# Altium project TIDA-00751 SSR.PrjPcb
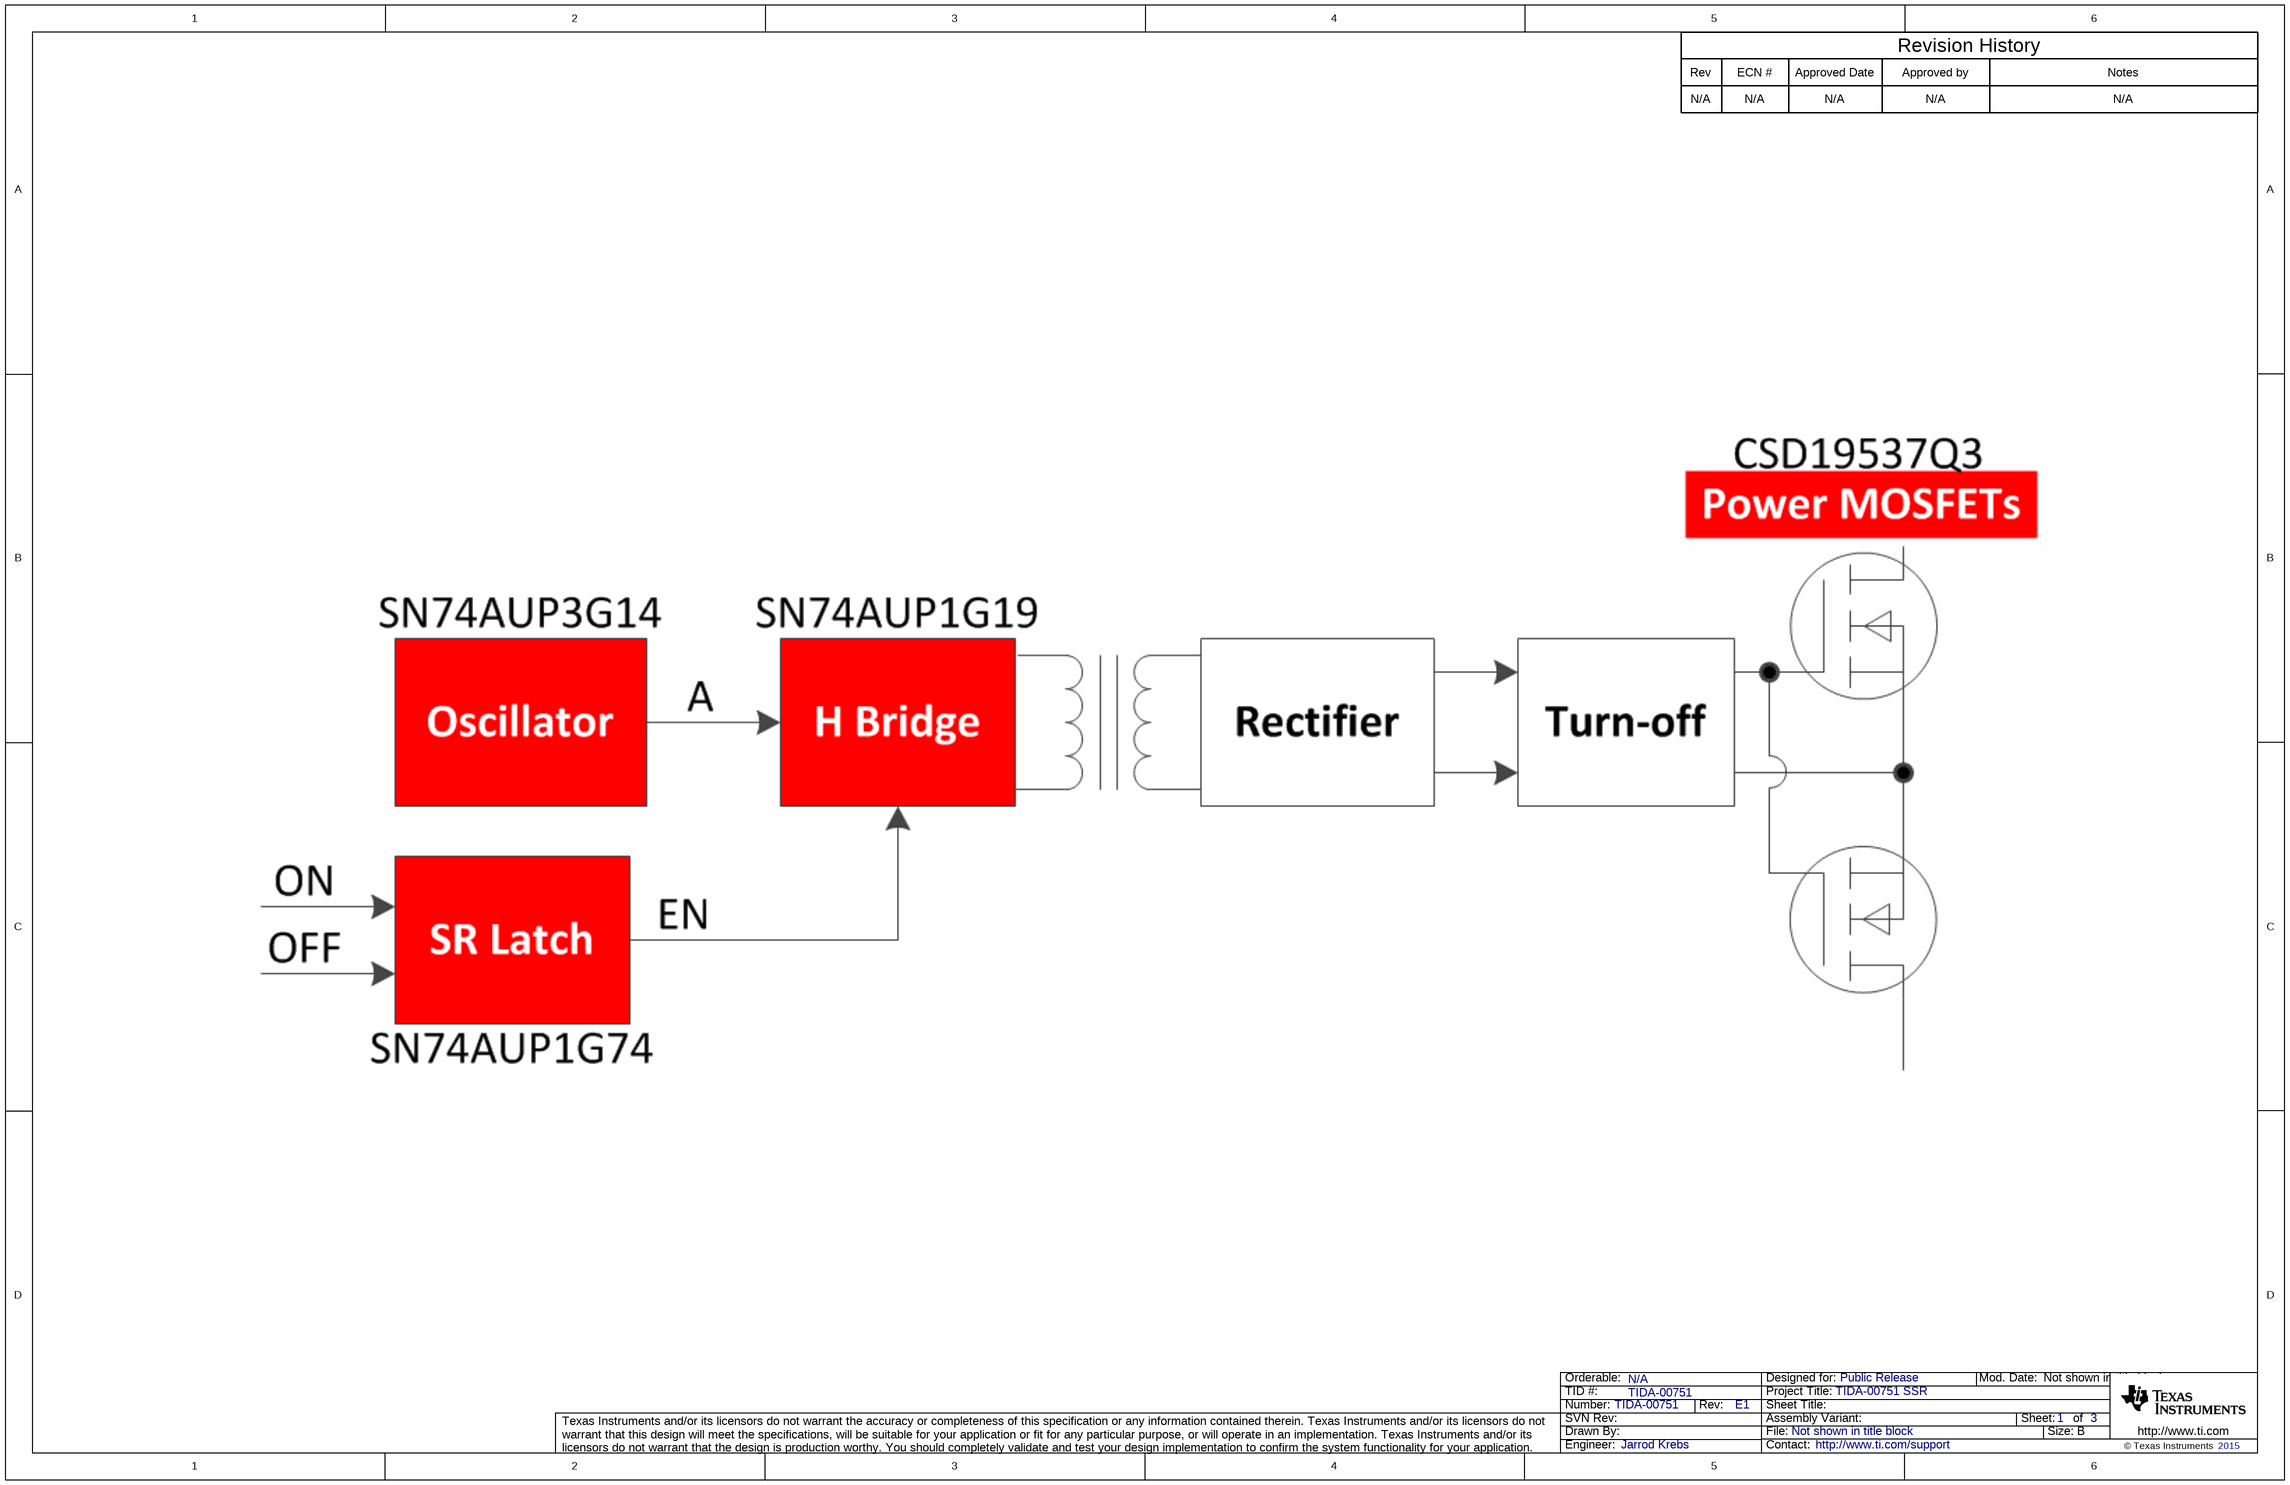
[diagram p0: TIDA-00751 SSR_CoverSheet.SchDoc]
CopyrightYear: 2015; EVM_Orderable: N/A; PCB_Layout: Who did the Layout?; PCB_Rev: E1; PRJ_Customer: Public Release; PRJ_Engineer: Jarrod Krebs; PRJ_Number: TIDA-00751; PRJ_Title: TIDA-00751 SSR; SCH_Rev: E1; TechSupport: http://www.ti.com/support; TID: TIDA-00751
3 sheets, 78 parts. Net scope: global (net labels, ports and power ports of the same name join across sheets).
Board file: TIDA-00751 SSR_TID.PcbDoc
Sheets:
  TIDA-00751 SSR_CoverSheet.SchDoc
  TIDA-00751 SSR_OSC+Relay.SchDoc
  TIDA-00751 SSR_TID_Hardware.SchDoc

## Sheet TIDA-00751 SSR_CoverSheet.SchDoc
size 431 x 279 mm; Date: Not shown in title block; ApprovedBy: Not shown in title block; CheckedBy: Not shown in title block; Author: Not shown in title block; CompanyName: Not shown in title block; Engineer: Not shown in title block; Organization: Not shown in title block; Address1: Not shown in title block; Address2: Not shown in title block; Address3: Not shown in title block; Address4: Not shown in title block; DocumentNumber: 1; Revision: Use project parameter SCH_Rev; SheetNumber: 1; SheetTotal: 3; PageSetup: Record=PageOptions¦CenterHorizontal=True¦CenterVertical=True¦PrintScale=1.00¦XCorrection=1.00¦YCorrection=1.00¦PrintKind=0¦BorderSize=5000000¦LeftOffset=0¦BottomOffset=0¦Orientation=2¦PaperLength=1000¦PaperWidth=1000¦Scale=100¦PaperSource=15¦PrintQuality=600¦MediaType=1¦DitherType=10¦PaperKind=Letter¦PrintScaleMode=1

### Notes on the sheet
- Rev
- N/A
- ECN #
- Approved Date
- Approved by
- Revision History
- Notes

## Sheet TIDA-00751 SSR_OSC+Relay.SchDoc
size 431 x 279 mm; Date: Not shown in title block; ApprovedBy: Not shown in title block; CheckedBy: Not shown in title block; Author: Not shown in title block; CompanyName: Not shown in title block; Engineer: Not shown in title block; Organization: Not shown in title block; Address1: Not shown in title block; Address2: Not shown in title block; Address3: Not shown in title block; Address4: Not shown in title block; DocumentNumber: 1; Revision: Use project parameter SCH_Rev; SheetNumber: 2; SheetTotal: 3; PageSetup: Record=PageOptions¦CenterHorizontal=True¦CenterVertical=True¦PrintScale=1.00¦XCorrection=1.00¦YCorrection=1.00¦PrintKind=0¦BorderSize=5000000¦LeftOffset=0¦BottomOffset=0¦Orientation=2¦PaperLength=1000¦PaperWidth=1000¦Scale=100¦PaperSource=15¦PrintQuality=-3¦MediaType=1¦DitherType=10¦PrintScaleMode=1¦PaperKind=Letter¦PaperIndex=1
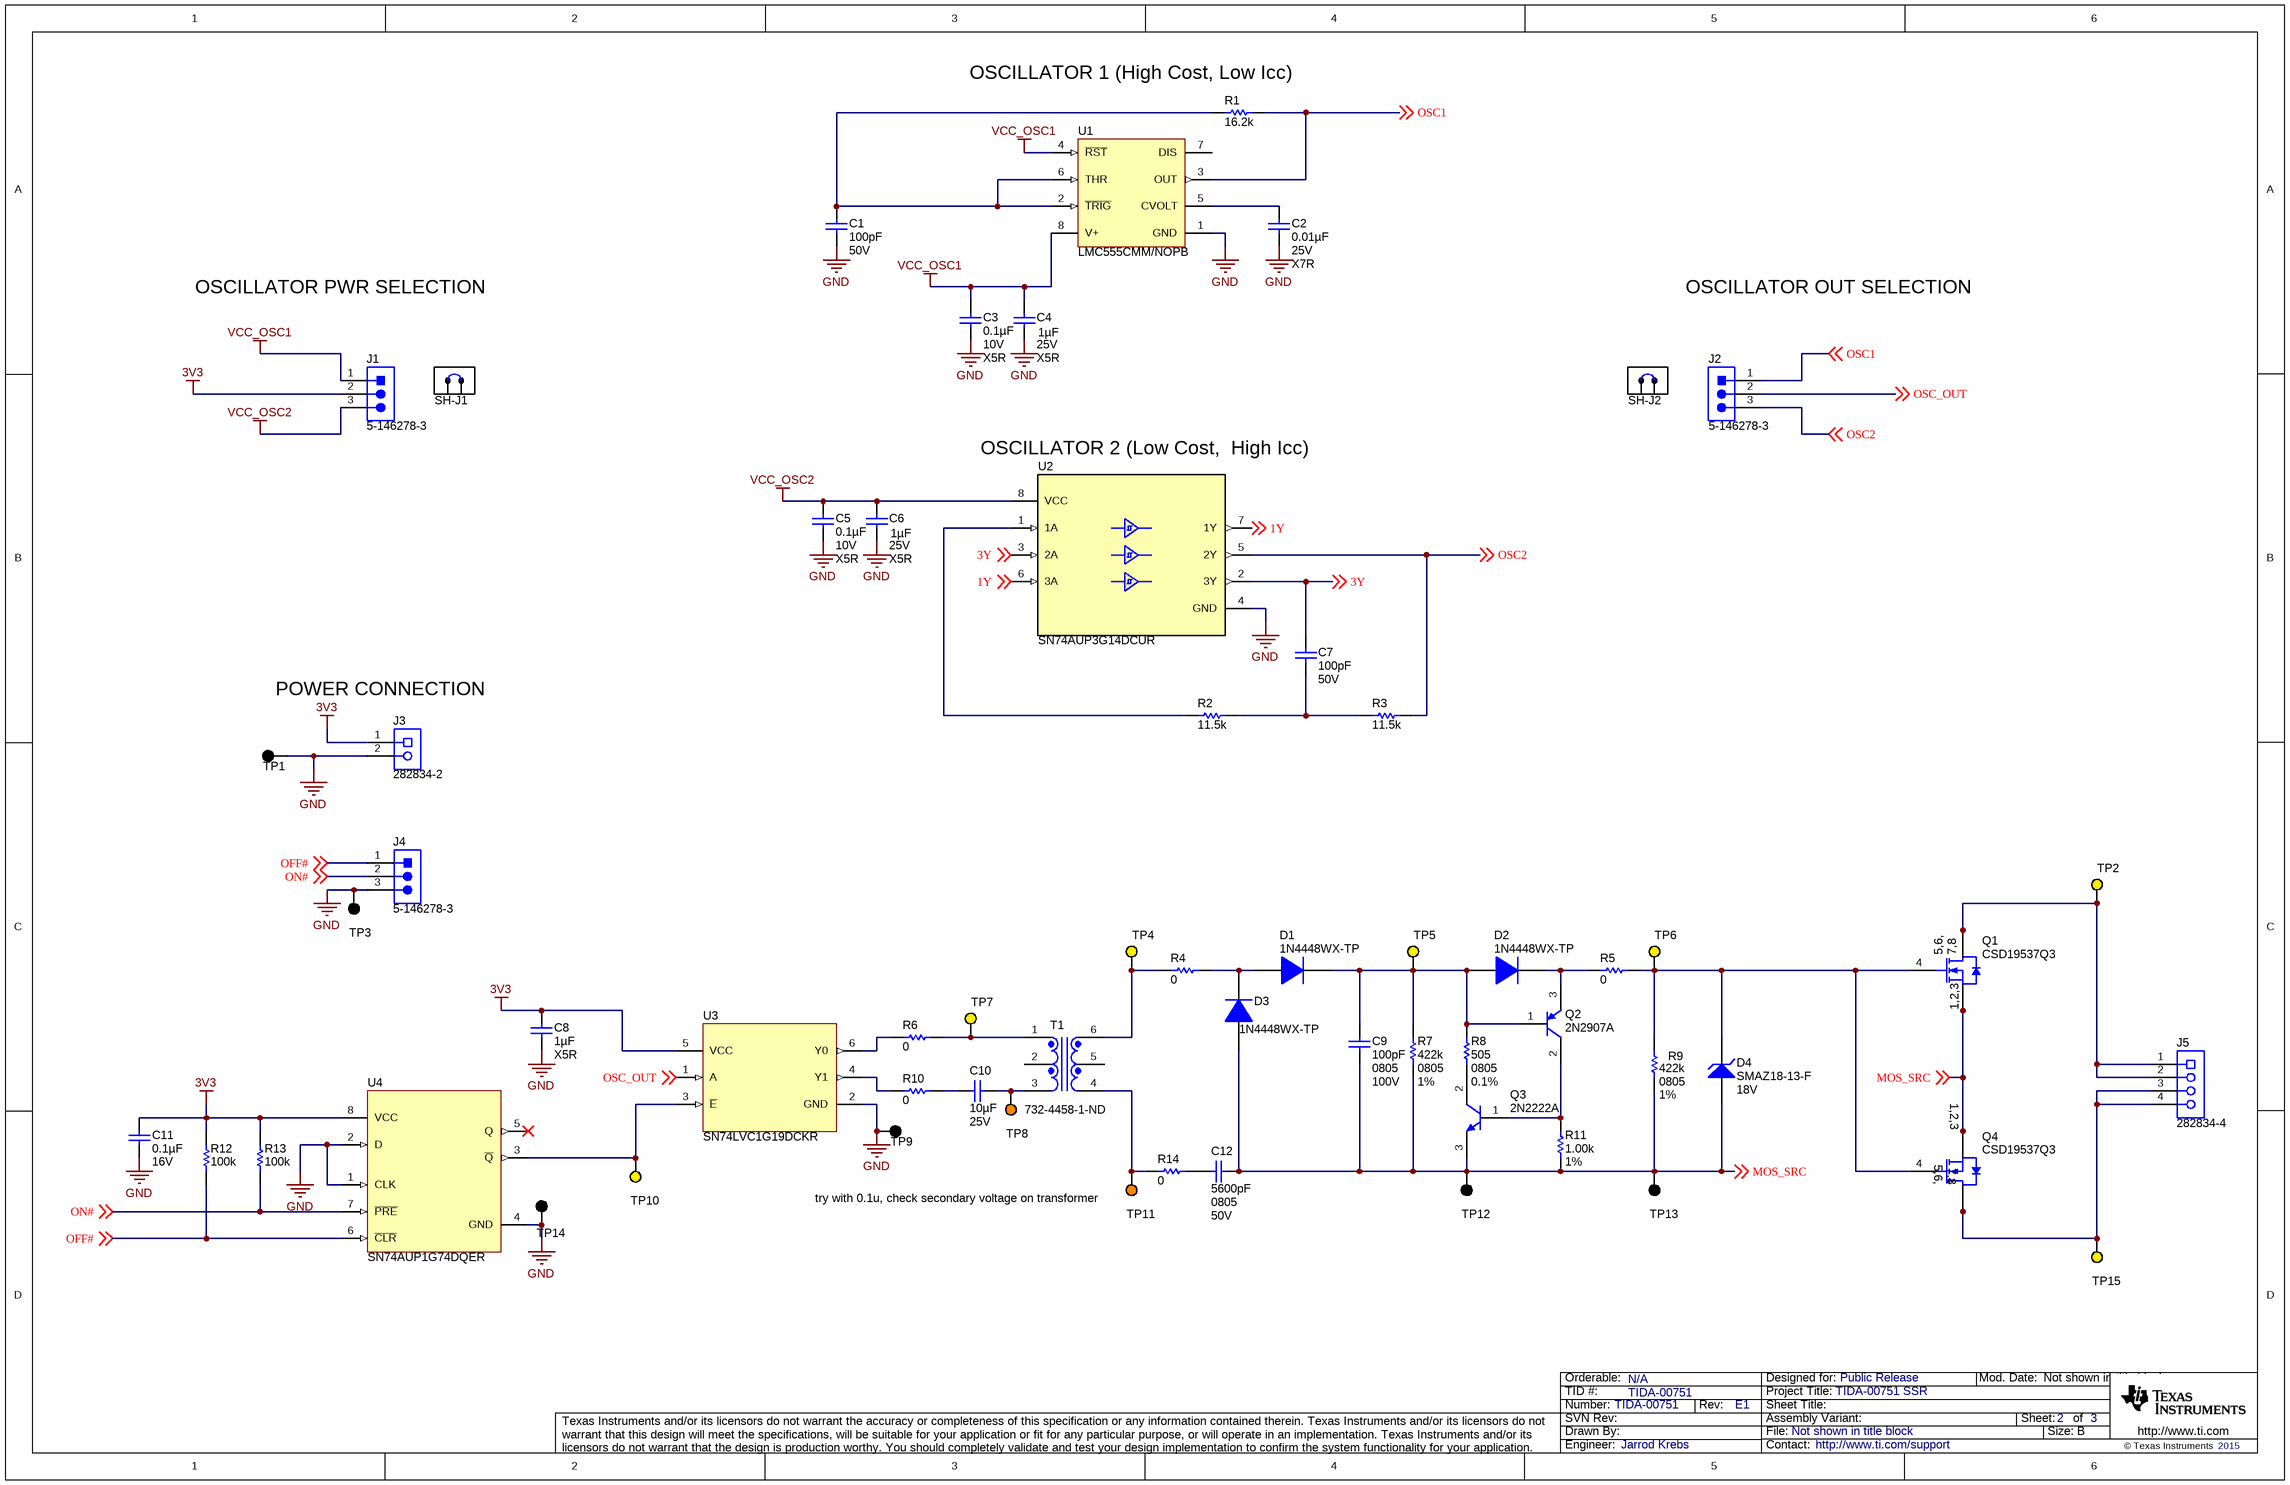
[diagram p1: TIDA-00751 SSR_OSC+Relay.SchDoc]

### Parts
C1  ValueDisplayed: 100pF  Value2: 50V  [0603]  (hidden comment: GRM1885C1H101JA01D)
C2  ValueDisplayed: 0.01µF  Value2: 25V  TempCo: X7R  [0603]  (hidden comment: GRM188R71E103KA01D)
C3  ValueDisplayed: 0.1µF  Value2: 10V  TempCo: X5R  [0402]  (hidden comment: C1005X5R1A104K050BA)
C4  ValueDisplayed: 1µF  Value2: 25V  TempCo: X5R  [0603]  (hidden comment: GRM188R61E105KA12D)
C5  ValueDisplayed: 0.1µF  Value2: 10V  TempCo: X5R  [0402]  (hidden comment: C1005X5R1A104K050BA)
C6  ValueDisplayed: 1µF  Value2: 25V  TempCo: X5R  [0603]  (hidden comment: GRM188R61E105KA12D)
C7  ValueDisplayed: 100pF  Value2: 50V  [0603]  (hidden comment: GRM1885C1H101JA01D)
C8  ValueDisplayed: 1µF  TempCo: X5R  [0603]  (hidden comment: GRM188R61E105KA12D)
C9  ValueDisplayed: 100pF  PackageReference: 0805  Value2: 100V  [0805_HV]  (hidden comment: 08051A101FAT2A)
C10  ValueDisplayed: 10µF  Value2: 25V  [0805_HV]  (hidden comment: GRM21BR61E106KA73L)
C11  ValueDisplayed: 0.1µF  Value2: 16V  [0603]  (hidden comment: GRM188R71C104KA01D)
C12  ValueDisplayed: 5600pF  PackageReference: 0805  Value2: 50V  [0805_HV]  (hidden comment: GRM2195C1H562JA01D)
D1  1N4448WX-TP  [sod-323]
D2  1N4448WX-TP  [sod-323]
D3  1N4448WX-TP  [sod-323]
D4  SMAZ18-13-F  value 18V  [SMA]
J1  5-146278-3  [TE_5-146278-3]
J2  5-146278-3  [TE_5-146278-3]
J3  282834-2  [TEC_282834-2]
J4  5-146278-3  [TE_5-146278-3]
J5  282834-4  [TEC_282834-4]
Q1  CSD19537Q3  [DQG0008A]
Q2  2N2907A  [TO-18]
Q3  2N2222A  [TO-18]
Q4  CSD19537Q3  [DQG0008A]
R1  ValueDisplayed: 16.2k  [0805_HV]  (hidden comment: CRCW080516K2FKEA)
R2  ValueDisplayed: 11.5k  [0805_HV]  (hidden comment: CRCW080511K5FKEA)
R3  ValueDisplayed: 11.5k  [0805_HV]  (hidden comment: CRCW080511K5FKEA)
R4  ValueDisplayed: 0  [0805_HV]  (hidden comment: CRCW08050000Z0EA)
R5  ValueDisplayed: 0  [0805_HV]  (hidden comment: CRCW08050000Z0EA)
R6  ValueDisplayed: 0  [0805_HV]  (hidden comment: CRCW08050000Z0EA)
R7  ValueDisplayed: 422k  PackageReference: 0805  Value1: 1%  [0805_HV]  (hidden comment: CRCW0805422KFKEA)
R8  ValueDisplayed: 505  PackageReference: 0805  Value1: 0.1%  [0805_HV]  (hidden comment: RT0805BRD07505RL)
R9  ValueDisplayed: 422k  PackageReference: 0805  Value1: 1%  [0805_HV]  (hidden comment: CRCW0805422KFKEA)
R10  ValueDisplayed: 0  [0805_HV]  (hidden comment: CRCW08050000Z0EA)
R11  ValueDisplayed: 1.00k  Value1: 1%  [0805_HV]  (hidden comment: ERJ-P06F1001V)
R12  ValueDisplayed: 100k  [0402]  (hidden comment: CRCW0402100KJNED)
R13  ValueDisplayed: 100k  [0402]  (hidden comment: CRCW0402100KJNED)
R14  ValueDisplayed: 0  [0805_HV]  (hidden comment: CRCW08050000Z0EA)
SH-J1  2SN-BK-G  [2SN-BK-G]  (value not drawn)
SH-J2  2SN-BK-G  [2SN-BK-G]  (value not drawn)
T1  Supplier Part Number 1: 732-4458-1-ND  [Wurth_760390013]  (hidden comment: 760390014)
TP1  5001  [Keystone5001]  (value not drawn)
TP2  5004  [Keystone5004]  (value not drawn)
TP3  5001  [Keystone5001]  (value not drawn)
TP4  5004  [Keystone5004]  (value not drawn)
TP5  5004  [Keystone5004]  (value not drawn)
TP6  5004  [Keystone5004]  (value not drawn)
TP7  5004  [Keystone5004]  (value not drawn)
TP8  5003  [Keystone5003]  (value not drawn)
TP9  5001  [Keystone5001]  (value not drawn)
TP10  5004  [Keystone5004]  (value not drawn)
TP11  5003  [Keystone5003]  (value not drawn)
TP12  5001  [Keystone5001]  (value not drawn)
TP13  5001  [Keystone5001]  (value not drawn)
TP14  5001  [Keystone5001]  (value not drawn)
TP15  5004  [Keystone5004]  (value not drawn)
U1  LMC555CMM/NOPB  [MUA08A_N]
U2  SN74AUP3G14DCUR  [DCU0008A_N]
U3  SN74LVC1G19DCKR  [DCK0006A_N]
U4  SN74AUP1G74DQER  [DQE0008A]

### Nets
3V3: C8.1 C11.2 J1.2 J3.1 R12.2 R13.2 U3.5(VCC) U4.8(VCC)
GND: C1.2 C2.2 C3.1 C4.1 C5.1 C6.1 C8.2 C11.1 J3.2 J4.3 TP1.1 TP3.1 TP9.1 TP14.1 U1.1(GND) U2.4(GND) U3.2(GND) U4.1(CLK) U4.2(D) U4.4(GND)
VCC_OSC1: C3.2 C4.2 J1.1 U1.4(~{RST}) U1.8(V+)
VCC_OSC2: C5.2 C6.2 J1.3 U2.8(VCC)
1Y: U2.6(3A) U2.7(1Y) ; off-sheet 1Y
3Y: C7.1 U2.2(3Y) U2.3(2A) ; off-sheet 3Y
MOS_SRC: C9.2 C12.1 D3.2(A) D4.2(A) Q1.1(S) Q1.2(S) Q1.3(S) Q3.3(B) Q4.1(S) Q4.2(S) Q4.3(S) R7.2 R9.1 R11.2 TP12.1 TP13.1 ; off-sheet MOS_SRC
OFF#: J4.1 R12.1 U4.6(~{CLR}) ; off-sheet OFF#
ON#: J4.2 R13.1 U4.7(~{PRE}) ; off-sheet ON#
OSC1: J2.1 R1.2 U1.3(OUT) ; off-sheet OSC1
OSC2: J2.3 R3.2 U2.5(2Y) ; off-sheet OSC2
OSC_OUT: J2.2 U3.1(A) ; off-sheet OSC_OUT
NetC1_1: C1.1 R1.1 U1.2(~{TRIG}) U1.6(THR)
NetC2_1: C2.1 U1.5(CVOLT)
NetC7_2: C7.2 R2.2 R3.1
NetC9_1: C9.1 D1.1(K) D2.2(A) Q2.1(E) R7.1 R8.1 TP5.1
NetC10_1: C10.1 R10.2
NetC10_2: C10.2 T1.3 TP8.1
NetC12_2: C12.2 R14.2
NetD1_2: D1.2(A) D3.1(K) R4.2
NetD2_1: D2.1(K) Q2.3(B) R5.1
NetD4_1: D4.1(K) Q1.4(G) Q4.4(G) R5.2 R9.2 TP6.1
NetJ5_1: J5.1 J5.2 Q1.5(D) Q1.6(D) Q1.7(D) Q1.8(D) Q1.9(D) TP2.1
NetJ5_3: J5.3 J5.4 Q4.5(D) Q4.6(D) Q4.7(D) Q4.8(D) Q4.9(D) TP15.1
NetQ2_2: Q2.2(C) Q3.1(E) R11.1
NetQ3_2: Q3.2(C) R8.2
NetR2_1: R2.1 U2.1(1A)
NetR4_1: R4.1 T1.6 TP4.1
NetR6_1: R6.1 U3.6(Y0)
NetR6_2: R6.2 T1.1 TP7.1
NetR10_1: R10.1 U3.4(Y1)
NetR14_1: R14.1 T1.4 TP11.1
NetTP10_1: TP10.1 U3.3(~{E}) U4.3(~{Q})

Not connected (* = marked no-connect by the designer): T1 2 5; U1 7(DIS); U4 5(Q)*

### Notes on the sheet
- (near R1) OSCILLATOR 1 (High Cost, Low Icc)
- OSCILLATOR PWR SELECTION
- OSCILLATOR OUT SELECTION
- (near U2) OSCILLATOR 2 (Low Cost,  High Icc)
- POWER CONNECTION
- (near TP11) try with 0.1u, check secondary voltage on transformer

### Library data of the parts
C1 C7 = GRM1885C1H101JA01D: CAP, CERM, 100 pF, 50 V, +/- 5%, C0G/NP0, 0603; Manufacturer: MuRata; Polarized: N; CompType: Capacitor; Value: 100pF; U/M: EA; Cap_F: 0.0000000001; Tolerance_%: 5; Value1: Unknown; VDC_V: 50; TaMin_C: -55; TaMax_C: 125; AEC Category: Q200
C2 = GRM188R71E103KA01D: CAP, CERM, 0.01 µF, 25 V, +/- 10%, X7R, 0603; Manufacturer: MuRata; Polarized: N; CompType: Capacitor; Value: 0.01uF; U/M: EA; Cap_F: 0.00000001; Tolerance_%: 10; Value1: Unknown; VDC_V: 25; TaMin_C: -55; TaMax_C: 125; AEC Category: Q200
C3 C5 = C1005X5R1A104K050BA: CAP, CERM, 0.1 µF, 10 V, +/- 10%, X5R, 0402; Manufacturer: TDK; Polarized: N; CompType: Capacitor; Value: 0.1uF; U/M: EA; Cap_F: 0.0000001; Tolerance_%: 10; Value1: Unknown; TaMin_C: -55; TaMax_C: 85; AEC Category: Q200
C4 C6 = GRM188R61E105KA12D: CAP, CERM, 1 µF, 25 V, +/- 10%, X5R, 0603; Manufacturer: MuRata; Polarized: N; CompType: Capacitor; Value: 1uF; U/M: EA; Cap_F: 0.000001; Tolerance_%: 10; Value1: Unknown; VDC_V: 25; TaMin_C: -55; TaMax_C: 85; AEC Category: Q200
C8 = GRM188R61E105KA12D: CAP, CERM, 1 µF, 25 V, +/- 10%, X5R, 0603; Manufacturer: MuRata; Polarized: N; CompType: Capacitor; Value: 1uF; U/M: EA; Cap_F: 0.000001; Tolerance_%: 10; Value1: Unknown; VDC_V: 25; Value2: 25V; TaMin_C: -55; TaMax_C: 85; AEC Category: Q200
C9 = 08051A101FAT2A: CAP, CERM, 100 pF, 100 V, +/- 1%, C0G/NP0, 0805; Manufacturer: AVX; Polarized: N; CompType: Capacitor; Value: 100pF; U/M: EA; Cap_F: 0.0000000001; Tolerance_%: 1; ESR_ohm: 0.356; Value1: 0.356 ohm; VDC_V: 100; TaMin_C: -55; TaMax_C: 125; AEC Category: Q200
C10 = GRM21BR61E106KA73L: CAP, CERM, 10 µF, 25 V, +/- 10%, X5R, 0805; Manufacturer: MuRata; Polarized: N; CompType: Capacitor; Value: 10uF; U/M: EA; Cap_F: 0.00001; Tolerance_%: 10; Value1: Unknown; VDC_V: 25; TaMin_C: -55; TaMax_C: 85; Cap_Case: 0805; AEC Category: Q200
C11 = GRM188R71C104KA01D: CAP, CERM, 0.1 µF, 16 V, +/- 10%, X7R, 0603; Manufacturer: MuRata; Polarized: N; CompType: Capacitor; Value: 0.1uF; U/M: EA; Cap_F: 0.0000001; Tolerance_%: 10; Value1: Unknown; VDC_V: 16; TaMin_C: -55; TaMax_C: 125; AEC Category: Q200
C12 = GRM2195C1H562JA01D: CAP, CERM, 5600 pF, 50 V, +/- 5%, C0G/NP0, 0805; Manufacturer: MuRata; Polarized: N; CompType: Capacitor; Value: 5600pF; U/M: EA; Cap_F: 0.0000000056; Tolerance_%: 5; Value1: Unknown; VDC_V: 50; TaMin_C: -55; TaMax_C: 125; AEC Category: Q200
D1-D3 = 1N4448WX-TP: Diode, Switching, 75 V, 0.25 A, SOD-323; Manufacturer: Micro Commercial Components; U/M: EA; Value: 75V; Value1: 0.25A; Io_A: 0.25; Vr_V: 75; TJmax_C: 150; AEC Category: Q101
D4 = SMAZ18-13-F: Diode, Zener, 18 V, 1 W, AEC-Q101, SMA; Manufacturer: Diodes Inc.; SymbolCreator: a0412235; U/M: EA; Power_W: 1; Vz_V: 18; Value1: 1W; RJA_CperW: 125; AEC Category: Q101; AEC Qualified: Y
J1 J2 J4 = 5-146278-3: Header, 100mil, 3x1, Tin, TH; Manufacturer: TE Connectivity; SymbolCreator: a0799628
J3 = 282834-2: Terminal Block, 2x1, 2.54mm, TH; Manufacturer: TE Connectivity; SymbolCreator: a0412235
J5 = 282834-4: Terminal Block, 100mil, 4X1 TH; Manufacturer: TE Connectivity; SymbolCreator: a0411947
Q1 Q4 = CSD19537Q3: MOSFET, N-CH, 100 V, 50 A, DQG0008A; Manufacturer: Texas Instruments; Alternate Manufacturer: None; U/M: EA; ChType: N; Value: 100V; VdsMax_V: 100; Value1: ? ohm; Value2: 16 nC; QgTyp_nC: 16; Vgs_V: 20; IdsMax_A: 50; AEC Category: Q101
Q2 = 2N2907A, Central Semiconductor: Transistor, PNP, 60 V, 0.6 A, TO-18; SymbolCreator: a0411947; PNP: 1; NPN: 0; Vceo_V: 60; Vcesat1_V: 0.4; Value: 60 V; IcRated_A: 0.6; Value1: 0.6 A; HfeMax: 300; TaMin_C: -65; TaMax_C: 200; CompType: BJT; U/M: EA; AEC Category: Q101
Q3 = 2N2222A, STMicroelectronics: Transistor, NPN, 40 V, 0.6 A, TO-18; SymbolCreator: a0411947; PNP: 0; NPN: 1; Vceo_V: 40; Value: 40 V; IcRated_A: 0.6; Value1: 0.6 A; HfeMax: 300; TaMin_C: -65; TaMax_C: 175; CompType: BJT; U/M: EA; AEC Category: Q101
R1 = CRCW080516K2FKEA: RES, 16.2 k, 1%, 0.125 W, 0805; Manufacturer: Vishay-Dale; CompType: Resistor; Value: 16.2k; Res_ohm: 16200; Value_Code: 16k2; Tolerance_%: 1; Power_W: 0.125; Value2: 0.125W; VDC_V: 150; TempCo: 100 ppm/C; EIA_Code: E96; U/M: EA; AEC Category: Q200
R2 R3 = CRCW080511K5FKEA: RES, 11.5 k, 1%, 0.125 W, 0805; Manufacturer: Vishay-Dale; CompType: Resistor; Value: 11.5k; Res_ohm: 11500; Value_Code: 11k5; Tolerance_%: 1; Power_W: 0.125; Value2: 0.125W; VDC_V: 150; TempCo: 100 ppm/C; EIA_Code: E96; U/M: EA; AEC Category: Q200
R4-R6 R10 R14 = CRCW08050000Z0EA: RES, 0, 5%, 0.125 W, 0805; Manufacturer: Vishay-Dale; CompType: Resistor; Value: 0; Value_Code: 0000; Tolerance_%: 5; Power_W: 0.125; Value2: 0.125W; VDC_V: 150; TempCo: 200 ppm/C; EIA_Code: E24; U/M: EA; AEC Category: Q200
R7 R9 = CRCW0805422KFKEA: RES, 422 k, 1%, 0.125 W, 0805; Manufacturer: Vishay-Dale; CompType: Resistor; Value: 422k; Res_ohm: 422000; Tolerance_%: 1; Power_W: 0.125; Value2: 0.125W; VDC_V: 150; TempCo: 100 ppm/C; EIA_Code: E96; U/M: EA; AEC Category: Q200
R8 = RT0805BRD07505RL: RES, 505, 0.1%, 0.125 W, 0805; Manufacturer: Yageo America; CompType: Resistor; Value: 505; Value_Code: 505R; Tolerance_%: 0.1; Power_W: 0.125; Value2: 0.125W; VDC_V: 150; TempCo: 25 ppm/C; EIA_Code: E192; U/M: EA; AEC Category: Q200
R11 = ERJ-P06F1001V: RES, 1.00 k, 1%, 0.25 W, 0805; Manufacturer: Panasonic; CompType: Resistor; Value: 1.00k; Res_ohm: 1000; Value_Code: 1k00; Tolerance_%: 1; Power_W: 0.25; Value2: 0.25W; VDC_V: 400; TempCo: 100 ppm/C; EIA_Code: E96; U/M: EA; AEC Category: Q200
R12 R13 = CRCW0402100KJNED: RES, 100 k, 5%, 0.063 W, 0402; Manufacturer: Vishay-Dale; CompType: Resistor; Value: 100k; Res_ohm: 100000; Tolerance_%: 5; Power_W: 0.063; Value2: 0.063W; VDC_V: 50; TempCo: 200 ppm/C; EIA_Code: E24; U/M: EA; AEC Category: Q200
SH-J1 SH-J2 = 2SN-BK-G: Shunt, 2mm, Gold plated, Black; Manufacturer: Samtec; Value: 1x2; Note: You can "mate" this to a header by matching the designator.  i.e. use SH-J3 for header J3
T1 = 760390014: Transformer, 475uH, SMT; Manufacturer: Wurth Elektronik; SymbolCreator: a0799628; ValueDisplayed: 475µH; Lp: 475; DCR_ohm: 0.31
TP1 TP3 TP9 TP12-TP14 = 5001: Test Point, Miniature, Black, TH; Manufacturer: Keystone; CompType: Test Point Loop; U/M: EA
TP2 TP4-TP7 TP10 TP15 = 5004: Test Point, Miniature, Yellow, TH; Manufacturer: Keystone; CompType: Test Point Loop; U/M: EA
TP8 TP11 = 5003: Test Point, Miniature, Orange, TH; Manufacturer: Keystone; CompType: Test Point Loop; U/M: EA
U1 = LMC555CMM/NOPB: CMOS Timer, 8-pin Mini SOIC, Pb-Free; Manufacturer: Texas Instruments; PackageTopMarking: ZXTT*ZC5; PowerWise: N; CompType: Analog IC
U2 = SN74AUP3G14DCUR: LOW-POWER TRIPLE SCHMITT-TRIGGER INVERTER, DCU0008A; Manufacturer: Texas Instruments; SymbolCreator: Altium; CompType: IC; U/M: EA
U3 = SN74LVC1G19DCKR: 1-OF-2 DECODER/DEMULTIPLEXER, DCK0006A; Manufacturer: Texas Instruments; SymbolCreator: Altium; CompType: IC; U/M: EA
U4 = SN74AUP1G74DQER: LOW-POWER SINGLE POSITIVE-EDGE-TRIGGERED D-TYPE FLIP-FLOP WITH CLEAR AND PRESET, DQE0008A; Manufacturer: Texas Instruments; SymbolCreator: a0799628; CompType: IC; U/M: EA

## Sheet TIDA-00751 SSR_TID_Hardware.SchDoc
size 431 x 279 mm; Date: Not shown in title block; ApprovedBy: Not shown in title block; CheckedBy: Not shown in title block; Author: Not shown in title block; CompanyName: Not shown in title block; Engineer: Not shown in title block; Organization: Not shown in title block; Address1: Not shown in title block; Address2: Not shown in title block; Address3: Not shown in title block; Address4: Not shown in title block; DocumentNumber: 1; Revision: Use project parameter SCH_Rev; SheetNumber: 3; SheetTotal: 3; PageSetup: Record=PageOptions¦CenterHorizontal=True¦CenterVertical=True¦PrintScale=1.00¦XCorrection=1.00¦YCorrection=1.00¦PrintKind=0¦BorderSize=5000000¦LeftOffset=0¦BottomOffset=0¦Orientation=2¦PaperLength=1000¦PaperWidth=1000¦Scale=100¦PaperSource=15¦PrintQuality=600¦MediaType=1¦DitherType=10¦PaperKind=Letter¦PrintScaleMode=1
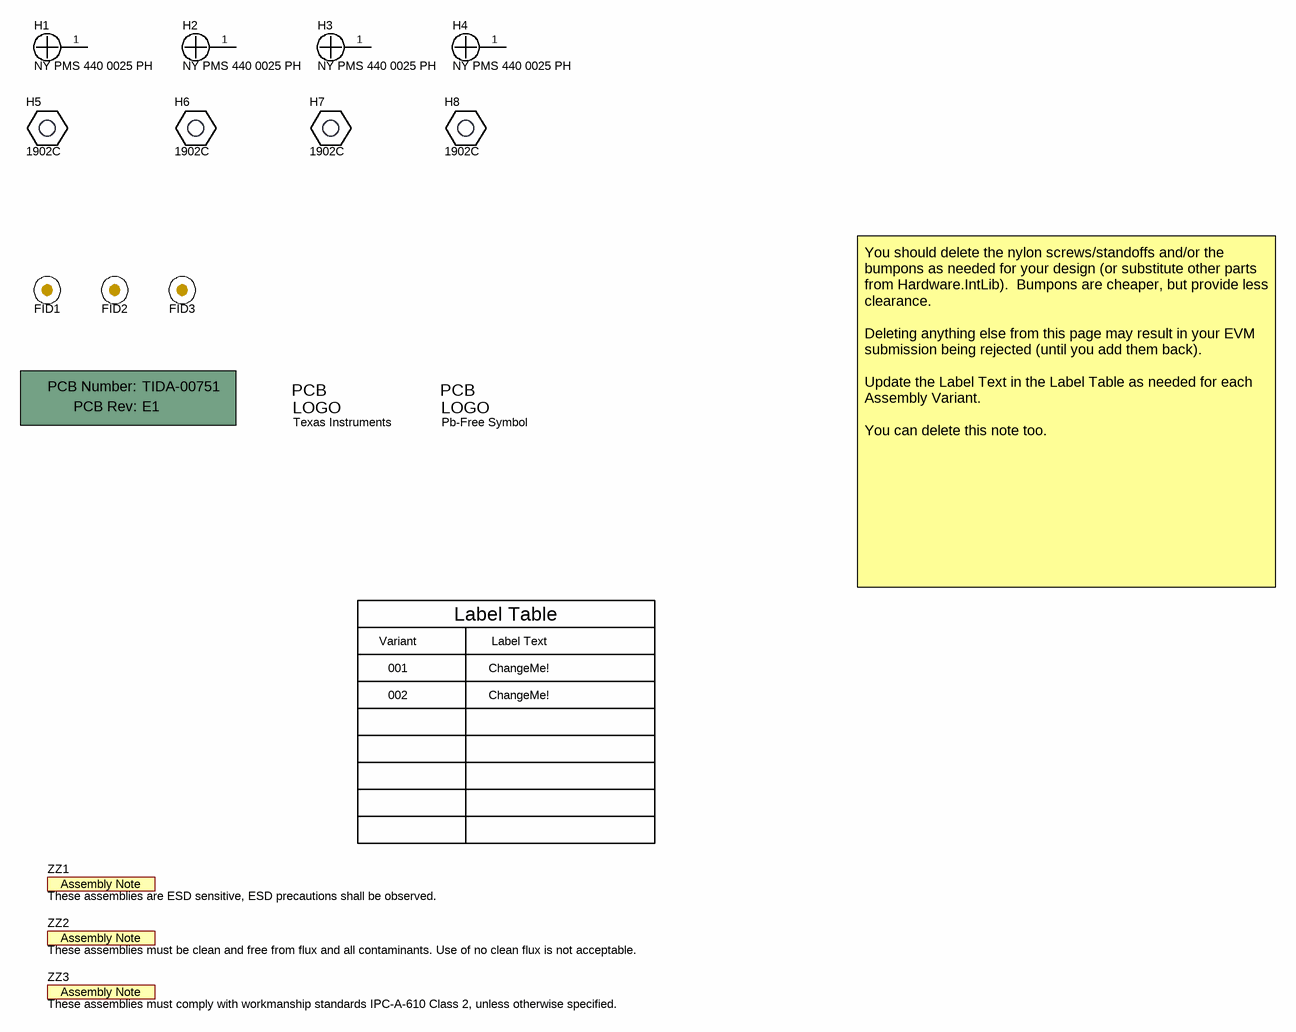
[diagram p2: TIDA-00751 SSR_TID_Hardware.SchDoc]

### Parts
!PCB1  Printed Circuit Board  (value not drawn)  (mechanical)
FID1  Fiducial  [Fiducial10-20]  (value not drawn)
FID2  Fiducial  [Fiducial10-20]  (value not drawn)
FID3  Fiducial  [Fiducial10-20]  (value not drawn)
H1  NY PMS 440 0025 PH  [NY PMS 440 0025 PH]
H2  NY PMS 440 0025 PH  [NY PMS 440 0025 PH]
H3  NY PMS 440 0025 PH  [NY PMS 440 0025 PH]
H4  NY PMS 440 0025 PH  [NY PMS 440 0025 PH]
H5  1902C  [Keystone_1902C]
H6  1902C  [Keystone_1902C]
H7  1902C  [Keystone_1902C]
H8  1902C  [Keystone_1902C]
Logo1  Texas Instruments  [TI_Stacked_Overlay_Small]  (no BOM)
Logo2  Pb-Free Symbol  [Pb-Free_Overlay_Small]  (no BOM)
ZZ1  These assemblies are ESD sensitive, ESD precautions shall be observed.  [AssemblyNote]  (no BOM)
ZZ2  These assemblies must be clean and free from flux and all contaminants. Use of no clean flux is not acceptable.  [AssemblyNote]  (no BOM)
ZZ3  These assemblies must comply with workmanship standards IPC-A-610 Class 2, unless otherwise specified.  [AssemblyNote]  (no BOM)

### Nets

Not connected (* = marked no-connect by the designer): H1 1; H2 1; H3 1; H4 1

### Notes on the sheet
- Variant
- Label Table
- Label Text
- You should delete the nylon screws/standoffs and/or the bumpons as needed for your design (or substitute other parts from Hardware.IntLib).  Bumpons are cheaper, but provide less clearance.
  Deleting anything else from this page may result in your EVM submission being rejected (until you add them back).
  Update the Label Text in the Label Table as needed for each Assembly Variant.
  You can delete this note too.
- 001
- 002
- ChangeMe!

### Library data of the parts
!PCB1 = PCB: Manufacturer: Any; PartNumber: TIDA-00751; SymbolCreator: a0412235
FID1-FID3 = Fiducial: Fiducial mark.  There is nothing to buy or mount.; SymbolCreator: codlsc
H1-H4 = NY PMS 440 0025 PH: Machine Screw, Round, #4-40 x 1/4, Nylon, Philips panhead; Manufacturer: B&F Fastener Supply; CompType: Hardware; SymbolCreator: codlsc; U/M: EA
H5-H8 = 1902C: Standoff, Hex, 0.5"L #4-40 Nylon; Manufacturer: Keystone; CompType: Hardware
Logo1 = TI_Logo: Texas Instrument Corporate Signature; SymbolCreator: codlsc
Logo2 = Pb-Free: SymbolCreator: a0412235
ZZ1-ZZ3 = AssemblyNote: SymbolCreator: codlsc

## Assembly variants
001: not fitted FID1 FID2 FID3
